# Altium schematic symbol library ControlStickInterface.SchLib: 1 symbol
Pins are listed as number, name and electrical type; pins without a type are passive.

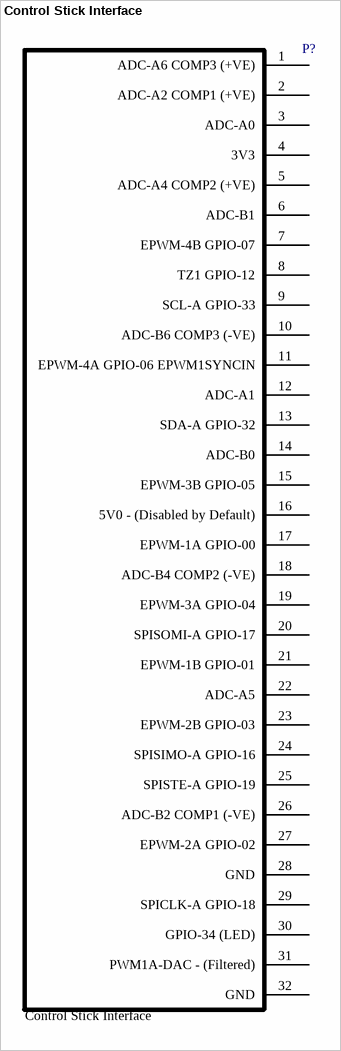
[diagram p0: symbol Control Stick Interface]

## Control Stick Interface
designator P?  Name: Control Stick Interface  (hidden comment: *)
footprint ControlStickInterface
pins: 1 ADC-A6 COMP3 (+VE), 2 ADC-A2 COMP1 (+VE), 3 ADC-A0, 4 3V3, 5 ADC-A4 COMP2 (+VE), 6 ADC-B1, 7 EPWM-4B GPIO-07, 8 TZ1 GPIO-12, 9 SCL-A GPIO-33, 10 ADC-B6 COMP3 (-VE), 11 EPWM-4A GPIO-06 EPWM1SYNCIN, 12 ADC-A1, 13 SDA-A GPIO-32, 14 ADC-B0, 15 EPWM-3B GPIO-05, 16 5V0 - (Disabled by Default), 17 EPWM-1A GPIO-00, 18 ADC-B4 COMP2 (-VE), 19 EPWM-3A GPIO-04, 20 SPISOMI-A GPIO-17, 21 EPWM-1B GPIO-01, 22 ADC-A5, 23 EPWM-2B GPIO-03, 24 SPISIMO-A GPIO-16, 25 SPISTE-A GPIO-19, 26 ADC-B2 COMP1 (-VE), 27 EPWM-2A GPIO-02, 28 GND, 29 SPICLK-A GPIO-18, 30 GPIO-34 (LED), 31 PWM1A-DAC - (Filtered), 32 GND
